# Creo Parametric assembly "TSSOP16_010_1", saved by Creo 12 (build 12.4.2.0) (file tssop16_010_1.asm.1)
Units: Custom; MM, KILOGRAM, SECS

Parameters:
  PTC_WM_ITERATION = "0"
  PTC_WM_VERSION = "-.0"
  PTC_WM_LIFECYCLE_STATE = "In Work"
  PTC_WM_LIFECYCLE = "MO_CADDocument"
  PTC_WM_CREATED_BY = "Maximilian Roepper (Z0017RMS: MO)"
  PTC_WM_CREATED_ON = "18-Sep-26 11:36:42 AM"
  PTC_WM_MODIFIED_BY = "Maximilian Roepper (Z0017RMS: MO)"
  PTC_WM_MODIFIED_ON = "18-Sep-26 11:36:46 AM"
  PDMLINKNUMBER = "PDM000071454956"
  PTC_WM_NUMBER = "PDM000071454956"

Other parameters: WEIGHT, WEIGHT_FACTOR, WEIGHT_ADD, MC_ERRORS, SUPPLIER

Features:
  1. coordinate system
  2. imported feature
  3. component "TSSOP16_001_1"
  4. component "TSSOP16_002_1"
  5. component "TSSOP16_003_1"
  6. component "TSSOP16_004_1"
  7. component "TSSOP16_005_1"
  8. component "TSSOP16_006_1"
  9. component "TSSOP16_007_1"
  10. component "TSSOP16_008_1"
  11. component "TSSOP16_009_1"
  12. component "SHAPESTRING253_1"

Other named items: DRW_VIEW_ORG, ROUGH-GROB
